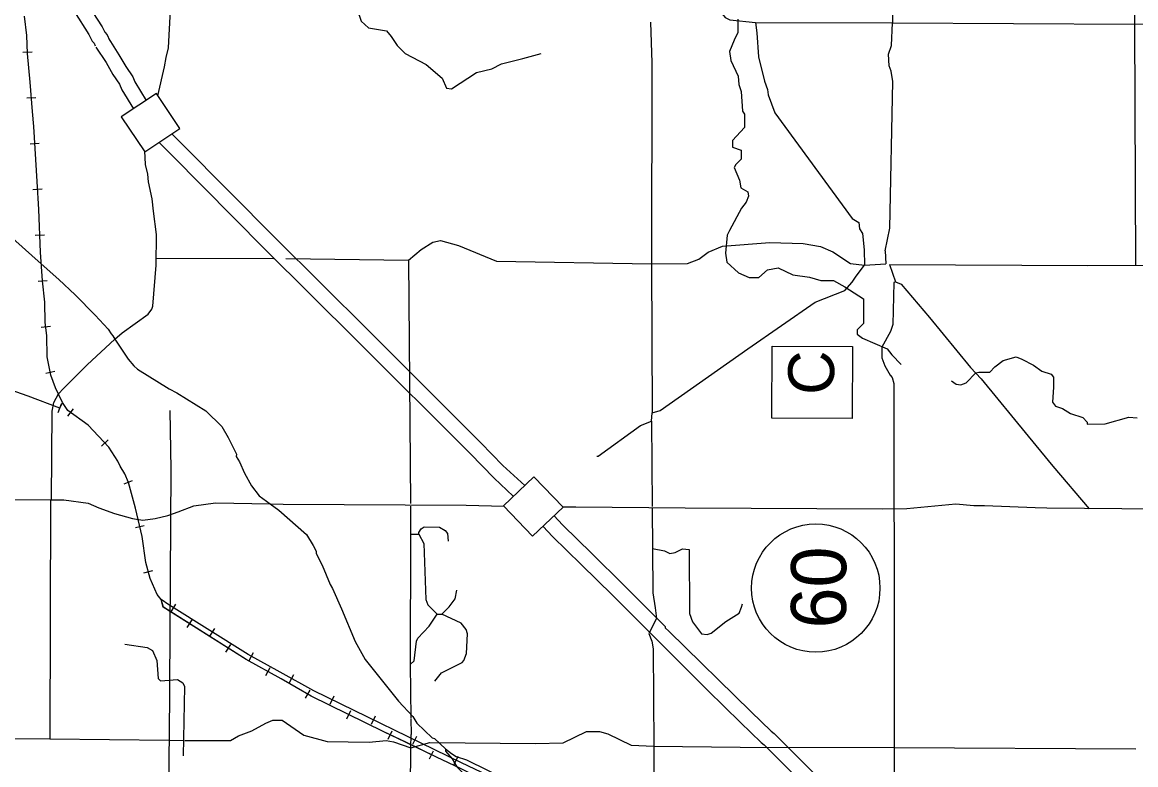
# Model space of a CAD drawing. Extents: x 299354 to 1325680, y 96128 to 228242.
# Drawn here: x 333137 to 357386, y 142472 to 158651 of the extents above; entities that cross this region are included whole.
import ezdxf

# ---------------------------------------------------------------- set-up
doc = ezdxf.new("R2010")
doc.units = 0
for name, color, linetype in [('Level 12', 7, 'Continuous'), ('Level 13', 7, 'Continuous'), ('Level 2', 7, 'Continuous'), ('Level 4', 7, 'Continuous'), ('Level 57', 7, 'Continuous'), ('Level 58', 7, 'Continuous')]:
    doc.layers.add(name, color=color, linetype=linetype)

msp = doc.modelspace()

# ---------------------------------------------------------------- linework, layer by layer
at = {"layer": 'Level 12'}
msp.add_line((350418, 146321), (350418, 146321), dxfattribs=at)
msp.add_circle((350418, 146321), 1398, dxfattribs=at)
at = {"layer": 'Level 13'}
msp.add_line((350317, 150840), (350317, 150840), dxfattribs=at)
msp.add_lwpolyline([(351211, 150019), (349461, 150026), (349468, 151596), (351218, 151589)], close=True, dxfattribs=at)
at = {"layer": 'Level 2'}
for points in [[(352072, 162146), (352089, 158637)], [(326463, 158936), (327303, 157778), (328003, 156788), (328308, 156377), (328423, 156210), (328754, 155915), (330363, 154934), (330562, 154832), (332054, 154685), (332253, 154567), (332856, 154003), (333485, 153447), (333932, 153043), (334287, 152715), (334725, 152269), (335006, 151967), (335073, 151862), (335107, 151815), (335153, 151743)], [(334272, 158877), (334588, 158388), (334661, 158239), (334706, 158193), (334726, 158141)], [(334676, 158861), (334876, 158551), (334934, 158432), (334989, 158376), (335034, 158261)], [(336089, 157048), (336235, 157681), (336270, 157880), (336322, 158097), (336363, 158913)], [(352031, 154163), (352094, 157362), (352063, 157587), (352014, 157704), (351999, 157955), (352068, 158146), (352089, 158637)], [(334741, 158112), (334961, 157772), (335110, 157511), (335252, 157301), (335304, 157176), (335560, 156767)], [(335019, 158291), (335243, 157943), (335390, 157685), (335544, 157459), (335589, 157350), (335833, 156947)], [(336393, 156218), (336618, 155995), (338651, 153943), (340667, 151942), (343122, 149485), (343606, 148993), (344084, 148559)], [(336109, 156035), (336385, 155761), (338417, 153710), (340434, 151708), (342888, 149253), (343412, 148719), (343831, 148321)], [(335153, 151743), (335314, 151881), (335876, 152292), (335961, 152400), (335978, 152466), (336053, 153357), (336059, 154024), (335997, 154533), (335966, 154800), (335886, 155175), (335871, 155342), (335823, 155551), (335809, 155851)], [(351927, 153672), (352031, 154163)], [(351927, 153672), (351941, 153388)], [(346857, 150143), (347032, 150191), (348938, 151532), (350407, 152552), (351051, 152805), (351211, 152987), (351296, 153119), (351482, 153359)], [(351482, 153359), (351941, 153388)], [(352024, 153371), (356344, 153349), (357378, 153356)], [(357378, 153356), (358379, 153347)], [(333771, 148244), (333788, 150178), (333824, 150369), (333925, 150551), (334035, 150667), (334548, 151187), (335153, 151743)], [(335153, 151743), (335310, 151506), (335442, 151313), (335566, 151162), (335648, 151094), (336337, 150663), (336503, 150578), (337133, 150181), (337480, 149844), (337619, 149601), (337800, 149241), (337799, 149191), (337865, 149074), (337979, 148823), (338127, 148547), (338300, 148328), (338534, 148155)], [(346838, 149959), (346857, 150143)], [(346838, 149959), (346855, 148099)], [(331094, 148269), (333771, 148244)], [(333771, 148244), (334046, 148242), (334571, 148170), (334803, 148068), (335144, 147949), (335537, 147835), (335765, 147800), (336035, 147841), (336311, 147905), (336529, 147986), (336872, 148116), (337348, 148179), (338534, 148155)], [(344911, 148094), (345195, 148091), (347572, 148069), (351875, 148047), (352400, 148059), (353469, 148158), (353860, 148121), (354094, 148119), (355194, 148075), (355453, 148073), (357904, 148051), (360415, 148078), (360690, 148076), (360718, 148076)], [(338534, 148155), (338816, 148151), (342802, 148129), (343629, 148109)], [(338534, 148155), (338722, 148016), (339326, 147486), (339474, 147251), (339540, 147125), (339539, 147075), (339670, 146824), (339842, 146398), (339891, 146314), (340087, 145870), (340389, 145159), (340602, 144766), (341328, 143859), (341642, 143523), (341732, 143381), (342063, 143061), (342113, 143044), (342352, 142817), (342485, 142715), (342584, 142648), (342809, 142579), (344170, 141908)], [(341590, 148105), (341595, 147499)], [(344716, 147904), (344909, 147692), (345542, 147073), (346229, 146391), (347137, 145484), (347137, 145457), (347216, 145386), (349013, 143625), (349443, 143203), (349510, 143152), (350460, 142203), (352152, 140532), (352377, 140324), (352377, 140303), (353402, 139293), (354705, 137983), (355027, 137690), (355633, 137107), (356892, 135850), (356978, 135780), (357454, 135262)], [(341595, 147499), (341585, 144657)], [(344480, 147665), (344687, 147447), (345310, 146838), (345996, 146157), (348069, 144088), (348782, 143389), (349227, 142953), (349293, 142903), (350227, 141969), (352960, 139269), (354477, 137745), (354801, 137449), (355402, 136871), (356671, 135605), (356751, 135540), (357216, 135033), (357381, 134871), (358086, 133923), (358208, 133766), (358636, 133244), (358726, 133129)], [(341585, 144657), (341600, 143492)], [(341600, 143476), (341605, 143132)], [(341602, 142840), (341605, 143132)], [(341585, 141059), (341602, 142840)]]:
    msp.add_lwpolyline(points, dxfattribs=at)
for points in [[(335294, 156588), (335805, 155824), (336569, 156335), (336058, 157099)], [(343615, 148113), (344251, 147450), (344915, 148085), (344279, 148749)]]:
    msp.add_lwpolyline(points, close=True, dxfattribs=at)
at = {"layer": 'Level 4'}
for p, q in [((333151, 158000), (333351, 158007)), ((333236, 157001), (333436, 157014)), ((333310, 156004), (333509, 156016)), ((333369, 155006), (333569, 155018)), ((333420, 154009), (333620, 154018)), ((333481, 153008), (333681, 153022)), ((333550, 152007), (333749, 152029)), ((333651, 151007), (333847, 151046)), ((333920, 150149), (333992, 150336)), ((334133, 150065), (334251, 150227)), ((334864, 149415), (335009, 149552)), ((335355, 148591), (335539, 148669)), ((335600, 147639), (335794, 147685)), ((335785, 146654), (335978, 146708)), ((336377, 145805), (336483, 145974)), ((336728, 145460), (336835, 145629)), ((337224, 145274), (337330, 145443)), ((337574, 144926), (337680, 145095)), ((338080, 144744), (338175, 144920)), ((338438, 144413), (338536, 144588)), ((338955, 144264), (339053, 144439)), ((339308, 143921), (339407, 144095)), ((339844, 143795), (339932, 143975)), ((340208, 143472), (340296, 143652)), ((340743, 143357), (340831, 143536)), ((341108, 143032), (341193, 143213)), ((341642, 142918), (341730, 143098)), ((342007, 142598), (342095, 142778)), ((342541, 142480), (342628, 142659))]:
    msp.add_line(p, q, dxfattribs=at)
for points in [[(357351, 161421), (357360, 158606)], [(346831, 159968), (347173, 159965), (347405, 159896), (347779, 159676), (348010, 159466), (348199, 159131), (348281, 158955), (348446, 158753), (348545, 158703), (349104, 158648)], [(333459, 155181), (333387, 156381), (333357, 156707), (333313, 157349), (333252, 157974), (333239, 158366), (333184, 158781)], [(342700, 142513), (339487, 144080), (338757, 144491), (338055, 144871), (336326, 145955), (336161, 146073), (336078, 146182), (335923, 146533), (335826, 146876), (335748, 147443), (335604, 148061), (335450, 148621), (335369, 148813), (335270, 148981), (335215, 149087), (335024, 149391), (334570, 149871), (334130, 150191), (334015, 150367), (333860, 150685), (333762, 150961), (333683, 151362), (333670, 151829), (333639, 152112), (333627, 152554), (333581, 153013), (333537, 153638), (333495, 154572), (333459, 155181), (333387, 156381), (333357, 156707), (333313, 157349), (333252, 157974), (333239, 158366), (333184, 158781)], [(346819, 158652), (346844, 157768), (346837, 153385)], [(349104, 158648), (349135, 158422), (349172, 157897), (349300, 157371), (349365, 157187), (349381, 157070), (349527, 156677), (351208, 154378), (351357, 154285)], [(349104, 158648), (352089, 158637)], [(352089, 158637), (357360, 158606)], [(357360, 158606), (359531, 158651)], [(357360, 158606), (357378, 153356)], [(333670, 151829), (333639, 152112), (333627, 152554), (333581, 153013), (333537, 153638), (333495, 154572), (333459, 155181)], [(351357, 154285), (351372, 154152), (351438, 154051), (351468, 153693)], [(341550, 153466), (341827, 153697), (342079, 153861), (342246, 153893), (342637, 153789), (343468, 153448), (346837, 153385)], [(346837, 153385), (347621, 153394), (347872, 153492), (348073, 153640), (348383, 153771), (349418, 153853), (350143, 153830), (350518, 153768), (350792, 153649), (351173, 153395), (351482, 153359)], [(336054, 153509), (338605, 153500)], [(338877, 153501), (341550, 153466)], [(351468, 153693), (351482, 153359)], [(341550, 153466), (341590, 148168)], [(346837, 153385), (346857, 150143)], [(352024, 153371), (352154, 152995)], [(352154, 152995), (352120, 152978), (352095, 152062), (352044, 151912), (351857, 151572), (351855, 151339), (351920, 151163), (352035, 150962), (352085, 150912), (352117, 150778), (352128, 144745), (352127, 142845)], [(352154, 152995), (352279, 152944), (352897, 152221), (353788, 151130), (354019, 150878), (355042, 149635), (355578, 148980), (356370, 148048)], [(334015, 150367), (333860, 150685), (333762, 150961), (333683, 151362), (333670, 151829)], [(333956, 150243), (333266, 150507), (331919, 150978), (331353, 151083), (330811, 151030), (329389, 150642), (328553, 150400), (327633, 150167)], [(333956, 150243), (333266, 150507), (331919, 150978)], [(333956, 150243), (334015, 150367)], [(334130, 150191), (334015, 150367)], [(335215, 149087), (335024, 149391), (334570, 149871), (334130, 150191)], [(336349, 150188), (336370, 148904), (336333, 143004)], [(345647, 149195), (345680, 149195), (346604, 149862), (346838, 149959)], [(335604, 148061), (335450, 148621), (335369, 148813), (335270, 148981), (335215, 149087)], [(333754, 148245), (333739, 143036)], [(335748, 147443), (335604, 148061)], [(346855, 148062), (346863, 147184)], [(336161, 146073), (336078, 146182), (335923, 146533), (335826, 146876), (335748, 147443)], [(341595, 147499), (341770, 147497)], [(341770, 147497), (341770, 147530), (341821, 147613), (341888, 147654), (342222, 147651), (342346, 147575), (342396, 147508), (342411, 147341)], [(341770, 147497), (341885, 147296), (341924, 146071), (341973, 145953), (342171, 145752)], [(346863, 147184), (346871, 146217), (346918, 145892), (346949, 145658), (346779, 145335), (346844, 145168), (346876, 145001), (346890, 142875)], [(346863, 147184), (347121, 147132), (347237, 147072), (347354, 147096), (347513, 147178), (347663, 147160), (347667, 145769), (347732, 145585), (347930, 145324), (348055, 145307), (348138, 145339), (348458, 145595), (348751, 145775), (348803, 145908), (348820, 145975)], [(342271, 145751), (342431, 145916), (342566, 146090), (342601, 146273)], [(338055, 144871), (336326, 145955), (336161, 146073)], [(338012, 144767), (336209, 145906), (336161, 146073)], [(342682, 142389), (342159, 142635), (341486, 142966), (341013, 143187), (339429, 143967), (338772, 144341), (338012, 144767), (336209, 145906), (336161, 146073)], [(341585, 144657), (341669, 144739), (341723, 145164), (341749, 145230), (342002, 145495), (342171, 145752)], [(342124, 144294), (342268, 144476), (342720, 144697), (342754, 144746), (342813, 144896), (342834, 145321), (342802, 145421), (342694, 145555), (342271, 145751)], [(342171, 145752), (342271, 145751)], [(339429, 143967), (338772, 144341), (338012, 144767)], [(339487, 144080), (338757, 144491), (338055, 144871)], [(345598, 141129), (344709, 141562), (342700, 142513), (339487, 144080)], [(345513, 141030), (343089, 142185), (342682, 142389), (342159, 142635), (341486, 142966), (341013, 143187), (339429, 143967)], [(336675, 143001), (337675, 143001), (337843, 143099), (338136, 143213), (338438, 143377), (338597, 143442), (338797, 143440), (339269, 143119), (339777, 142982), (340694, 142965), (341061, 143003), (341219, 142968), (341602, 142840)], [(342012, 142953), (344313, 142932), (344914, 142952), (345425, 143197), (345708, 143195), (345891, 143143), (346398, 142897), (346890, 142875)], [(331262, 143059), (333739, 143036)], [(333739, 143036), (336333, 143004)], [(336332, 142872), (336317, 137721)], [(336333, 143004), (336332, 142741)], [(336333, 143004), (336641, 143002)], [(341602, 142840), (342012, 142953)], [(346890, 142875), (346875, 139459)], [(346890, 142875), (348774, 142858)], [(348774, 142858), (352127, 142845)], [(352127, 142845), (352134, 140936), (352199, 140677), (352164, 140494), (352053, 140237), (352049, 139854), (352114, 139611), (352104, 137611), (354997, 137569), (355048, 137601), (355223, 137633), (355456, 137581), (357407, 137547)], [(352127, 142845), (357389, 142822)], [(342352, 142817), (342352, 142767), (342500, 142599), (342599, 142423), (343293, 141725), (343862, 141078), (344259, 140699), (344715, 140395), (346169, 139799), (346875, 139459)], [(344709, 141562), (342700, 142513)]]:
    msp.add_lwpolyline(points, dxfattribs=at)
at = {"layer": 'Level 57'}
for points in [[(340418, 160868), (340401, 160826), (340401, 160810), (340324, 160652), (340239, 160453), (340233, 159811), (340282, 159694), (340372, 159502), (340434, 158926), (340515, 158675), (340680, 158532), (341071, 158462), (341170, 158344), (341302, 158143), (341476, 157967), (341932, 157729), (342280, 157434), (342378, 157217), (342486, 157199), (343031, 157553), (343366, 157633), (343575, 157748), (344035, 157860), (344436, 157973)], [(348721, 158718), (348719, 158426), (348642, 158260), (348540, 158011), (348571, 157819), (348727, 157476), (348742, 157292), (348790, 157142), (348820, 156717), (348869, 156650), (348867, 156358), (348605, 156077), (348604, 155927), (348795, 155867), (348793, 155667), (348676, 155551), (348642, 155485), (348756, 155209), (348788, 155042), (348937, 154957), (348953, 154865), (348902, 154733), (348800, 154600), (348537, 154111), (348486, 154011), (348449, 153620), (348481, 153420), (348737, 153192), (348970, 153090), (349178, 153088), (349363, 153253), (349597, 153301), (349921, 153148), (350279, 153095), (350529, 153026), (350804, 153024), (351053, 152888), (351459, 152626), (351457, 152443), (351455, 152218), (351454, 152084), (351319, 151952), (351319, 151852), (351435, 151768), (351975, 151538), (352073, 151404), (352280, 151194)], [(353377, 150834), (353477, 150766), (353577, 150749), (353694, 150797), (353905, 151012), (353971, 151028), (354105, 151027), (354205, 151026), (354314, 151142), (354499, 151282), (354783, 151363), (354908, 151311), (355157, 151176), (355339, 151049), (355547, 150981), (355597, 150914), (355595, 150697), (355575, 150372), (355641, 150288), (355791, 150237), (355965, 150127), (356231, 150041), (356330, 149940), (356329, 149890)], [(356329, 149890), (356722, 149903), (357232, 150049), (357415, 150030)], [(335369, 145097), (335860, 145025), (335976, 144958), (336066, 144740), (336096, 144348), (336145, 144298), (336521, 144328), (336637, 144260), (336670, 144176), (336639, 142668), (336639, 142665)]]:
    msp.add_lwpolyline(points, dxfattribs=at)
at = {"layer": 'Level 58'}
for points in [[(338012, 144767), (336209, 145906), (336161, 146073)], [(338013, 144767), (336210, 145906), (336162, 146073)], [(339429, 143967), (338772, 144341), (338012, 144767)], [(339430, 143967), (338773, 144341), (338013, 144767)], [(345513, 141030), (343089, 142185), (342682, 142389), (342159, 142635), (341486, 142966), (341013, 143187), (339429, 143967)], [(345514, 141030), (343090, 142185), (342683, 142389), (342160, 142635), (341487, 142966), (341014, 143187), (339430, 143967)]]:
    msp.add_lwpolyline(points, dxfattribs=at)

# ---------------------------------------------------------------- texts
at = {"layer": 'Level 12'}
msp.add_text('60', height=1200, rotation=89.767, dxfattribs=at).set_placement((351075, 145439))
at = {"layer": 'Level 13'}
msp.add_text('C', height=1000, rotation=89.767, dxfattribs=at).set_placement((350816, 150531))

doc.saveas('drawing.dxf')
